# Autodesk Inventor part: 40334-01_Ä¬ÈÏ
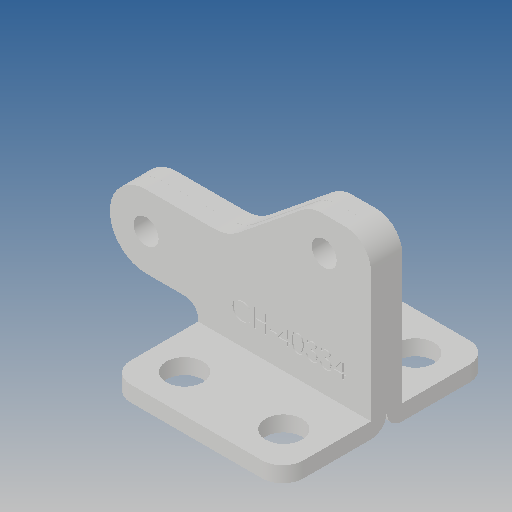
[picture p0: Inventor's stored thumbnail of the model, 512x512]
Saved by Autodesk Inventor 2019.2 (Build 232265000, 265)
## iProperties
Created: 2010-06
Part Number: 40334-01_Ä¬ÈÏ
Material: Ogólny
Document SubType Name: Modeling
Designer: CADENGINEERING4
Density: 1 g/cm^3
Appearance: Domyślna
Author: CADENGINEERING4
Revision Number: ÈÎºÎ
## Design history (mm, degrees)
feature "NONE"
feature "NONE:1"
node "Bryła1"
node "Bryła2"
